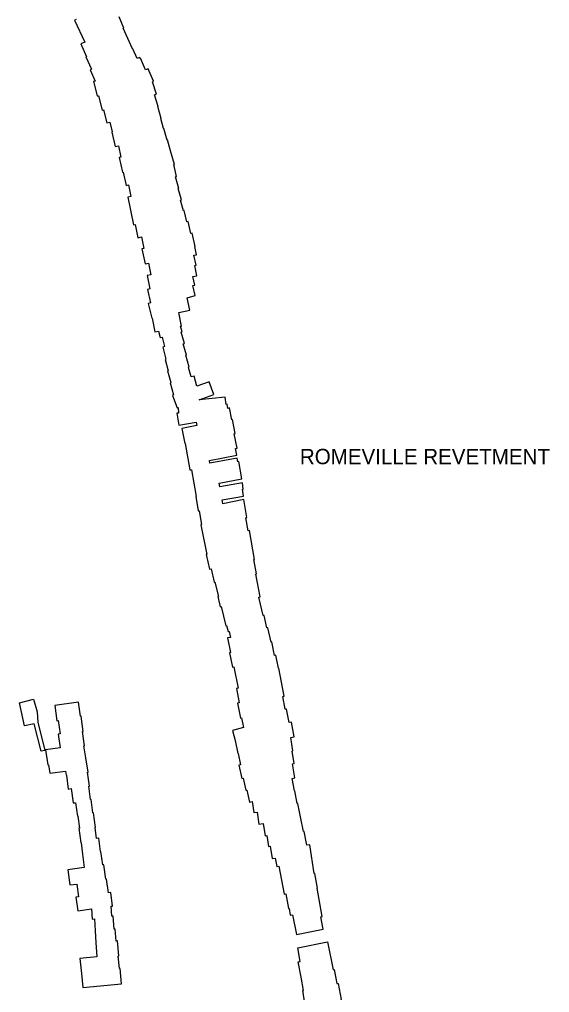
# Model space of a CAD drawing. Extents: x 2650582 to 3923188, y 277893 to 989177.
# Drawn here: x 3436610 to 3442129, y 552929 to 563066 of the extents above; entities that cross this region are included whole.
import ezdxf

# ---------------------------------------------------------------- set-up
doc = ezdxf.new("R2010")
doc.units = 0
doc.layers.add('Level 3', color=7, linetype='Continuous')

msp = doc.modelspace()

# ---------------------------------------------------------------- linework, layer by layer
at = {"layer": 'Level 3'}
for points in [[(3437201, 563066), (3437184, 563059), (3437291, 562828), (3437251, 562811), (3437307, 562678), (3437302, 562676), (3437360, 562548), (3437345, 562540), (3437399, 562424)], [(3438297, 561187), (3438262, 561305), (3438268, 561306), (3438234, 561427), (3438247, 561431), (3438216, 561554), (3438224, 561556), (3438184, 561699), (3438182, 561698), (3438150, 561811), (3438148, 561810), (3438112, 561930), (3438110, 561929), (3438082, 562034), (3438084, 562035), (3438050, 562158), (3438056, 562160), (3438017, 562281), (3438038, 562289), (3437994, 562417), (3438005, 562422), (3437952, 562553), (3437922, 562540), (3437870, 562663), (3437863, 562660), (3437859, 562671), (3437835, 562661), (3437789, 562761), (3437786, 562760), (3437691, 562974), (3437697, 562977), (3437649, 563092)], [(3437399, 562424), (3437381, 562419), (3437420, 562269), (3437434, 562272), (3437473, 562121), (3437486, 562124), (3437521, 561989), (3437551, 561995), (3437575, 561895), (3437572, 561893), (3437607, 561742), (3437641, 561750), (3437666, 561630), (3437648, 561627), (3437682, 561474), (3437691, 561476), (3437722, 561338), (3437746, 561343), (3437771, 561221), (3437739, 561214)], [(3437739, 561214), (3437799, 560928), (3437814, 560931), (3437844, 560793), (3437881, 560801), (3437906, 560681), (3437886, 560676), (3437920, 560522), (3437953, 560528), (3437977, 560406), (3437941, 560398), (3437969, 560259), (3437945, 560254), (3437976, 560113), (3437951, 560107), (3437987, 559953), (3437991, 559954), (3438021, 559811), (3438059, 559820)], [(3438357, 560168), (3438441, 560191), (3438417, 560295), (3438437, 560299), (3438416, 560388), (3438458, 560396), (3438436, 560503), (3438450, 560505), (3438427, 560610), (3438453, 560615), (3438436, 560701), (3438441, 560702), (3438410, 560840), (3438393, 560837), (3438366, 560960), (3438354, 560957), (3438326, 561076), (3438319, 561074), (3438288, 561184), (3438297, 561187)], [(3438288, 559870), (3438298, 559872), (3438269, 560015), (3438383, 560038), (3438357, 560168)], [(3438798, 559019), (3438780, 559015), (3438772, 559057), (3438761, 559056), (3438753, 559130), (3438480, 559104), (3438635, 559159), (3438584, 559292), (3438456, 559245), (3438430, 559351), (3438398, 559343), (3438370, 559440), (3438377, 559443), (3438342, 559568), (3438349, 559569), (3438315, 559688), (3438327, 559692), (3438293, 559810), (3438304, 559813), (3438288, 559870)], [(3438059, 559820), (3438077, 559752), (3438097, 559758), (3438122, 559659), (3438103, 559653), (3438135, 559527), (3438126, 559524), (3438158, 559406), (3438153, 559405), (3438188, 559284), (3438180, 559281), (3438214, 559156), (3438205, 559150), (3438253, 559022), (3438261, 559024), (3438265, 558966), (3438248, 558964), (3438271, 558840), (3438450, 558872)], [(3438927, 558281), (3438893, 558461), (3438884, 558459), (3438877, 558496), (3438594, 558443), (3438588, 558472), (3438874, 558526), (3438860, 558596), (3438877, 558599), (3438846, 558750), (3438857, 558752), (3438827, 558898), (3438821, 558897), (3438798, 559019)], [(3438450, 558872), (3438457, 558835), (3438300, 558805), (3438331, 558648), (3438335, 558648), (3438384, 558373), (3438402, 558376)], [(3438402, 558376), (3438451, 558096), (3438446, 558095), (3438472, 557947), (3438481, 557948), (3438505, 557804), (3438497, 557803), (3438560, 557494), (3438555, 557493), (3438589, 557340), (3438605, 557343), (3438637, 557203), (3438646, 557204), (3438682, 557056), (3438675, 557054), (3438700, 556949), (3438710, 556952), (3438759, 556751), (3438767, 556753), (3438782, 556690), (3438793, 556692), (3438807, 556629), (3438777, 556623), (3438809, 556471), (3438797, 556469), (3438830, 556319), (3438843, 556321), (3438889, 556100), (3438870, 556096), (3438897, 555947), (3438881, 555944), (3438911, 555789), (3438922, 555791), (3438942, 555690)], [(3439471, 555315), (3439450, 555445), (3439457, 555447), (3439436, 555586), (3439470, 555592), (3439442, 555747), (3439417, 555743), (3439391, 555883), (3439377, 555881), (3439354, 556013), (3439365, 556015), (3439312, 556309), (3439307, 556308), (3439278, 556443), (3439266, 556440), (3439237, 556582), (3439230, 556580), (3439197, 556729), (3439186, 556727), (3439157, 556858), (3439146, 556856), (3439104, 557049), (3439115, 557051), (3439070, 557288), (3439079, 557290), (3439050, 557441), (3439058, 557442), (3439004, 557742), (3438992, 557740), (3438967, 557876), (3438978, 557878), (3438948, 558064), (3438727, 558022), (3438720, 558061), (3438943, 558101), (3438933, 558173), (3438941, 558174), (3438931, 558239), (3438696, 558197), (3438689, 558235), (3438927, 558281)], [(3436757, 555984), (3436793, 555854), (3436800, 555746), (3436874, 555449), (3436836, 555443), (3436763, 555727), (3436664, 555707), (3436610, 555946), (3436757, 555984)], [(3437226, 555953), (3436979, 555920), (3437000, 555761), (3437015, 555763), (3437034, 555625), (3437014, 555622), (3437034, 555480), (3436882, 555456), (3436906, 555301), (3436914, 555303), (3436927, 555213), (3437090, 555237), (3437096, 555193), (3437099, 555193), (3437118, 555049), (3437149, 555054), (3437169, 554904), (3437193, 554907), (3437213, 554766), (3437218, 554767), (3437235, 554643), (3437230, 554642), (3437251, 554488), (3437252, 554488), (3437268, 554371), (3437266, 554371), (3437285, 554233), (3437113, 554209), (3437135, 554050), (3437206, 554060), (3437224, 553926), (3437198, 553922), (3437217, 553781), (3437359, 553800), (3437368, 553695), (3437390, 553697), (3437399, 553573), (3437397, 553573), (3437407, 553449), (3437404, 553449), (3437416, 553302), (3437240, 553285), (3437255, 553126), (3437256, 553126), (3437270, 552982)], [(3437270, 552982), (3437674, 553021), (3437659, 553180), (3437651, 553179), (3437639, 553309), (3437645, 553310), (3437632, 553467), (3437617, 553466), (3437607, 553589), (3437598, 553589), (3437587, 553726), (3437572, 553725), (3437564, 553828), (3437580, 553830), (3437561, 553972), (3437536, 553969), (3437517, 554110), (3437511, 554110), (3437490, 554261), (3437477, 554259), (3437458, 554397), (3437454, 554397), (3437435, 554538), (3437412, 554535), (3437397, 554648), (3437402, 554648), (3437381, 554802), (3437375, 554801), (3437356, 554942), (3437350, 554941), (3437332, 555079), (3437340, 555080), (3437320, 555225), (3437325, 555226), (3437303, 555376), (3437301, 555376), (3437281, 555499), (3437287, 555500), (3437267, 555649), (3437274, 555650), (3437253, 555808), (3437245, 555807), (3437226, 555953)], [(3438942, 555690), (3438830, 555660), (3438857, 555555), (3438856, 555555), (3438885, 555418), (3438888, 555419), (3438913, 555301), (3438895, 555297), (3438924, 555160), (3438940, 555164), (3438967, 555037), (3438977, 555039), (3439004, 554912), (3439033, 554918), (3439051, 554804), (3439084, 554809), (3439104, 554684), (3439148, 554691), (3439169, 554562), (3439186, 554565), (3439204, 554452), (3439219, 554455), (3439240, 554325)], [(3439240, 554325), (3439272, 554330), (3439289, 554242), (3439310, 554246), (3439368, 553954), (3439384, 553957), (3439410, 553805), (3439417, 553806), (3439430, 553737), (3439452, 553740), (3439494, 553535), (3439771, 553589), (3439747, 553719), (3439763, 553722), (3439711, 554017), (3439713, 554017), (3439685, 554169), (3439679, 554168), (3439632, 554468), (3439601, 554464), (3439576, 554608), (3439568, 554608), (3439537, 554759), (3439535, 554758), (3439510, 554899), (3439501, 554897), (3439477, 555030), (3439475, 555030), (3439450, 555160), (3439478, 555165), (3439452, 555311), (3439471, 555315)], [(3439610, 552680), (3439588, 552794), (3439584, 552794), (3439559, 552949), (3439569, 552951), (3439544, 553091), (3439542, 553090), (3439513, 553250), (3439533, 553254), (3439508, 553394), (3439816, 553456)], [(3439816, 553456), (3439875, 553166), (3439886, 553168), (3439914, 553023), (3439929, 553025), (3439959, 552857), (3439956, 552856), (3439975, 552744), (3439981, 552745), (3440010, 552595), (3440006, 552594)]]:
    msp.add_lwpolyline(points, dxfattribs=at)

# ---------------------------------------------------------------- texts
msp.add_text('ROMEVILLE REVETMENT', height=160, dxfattribs=at).set_placement((3439530, 558433))

doc.saveas('drawing.dxf')
